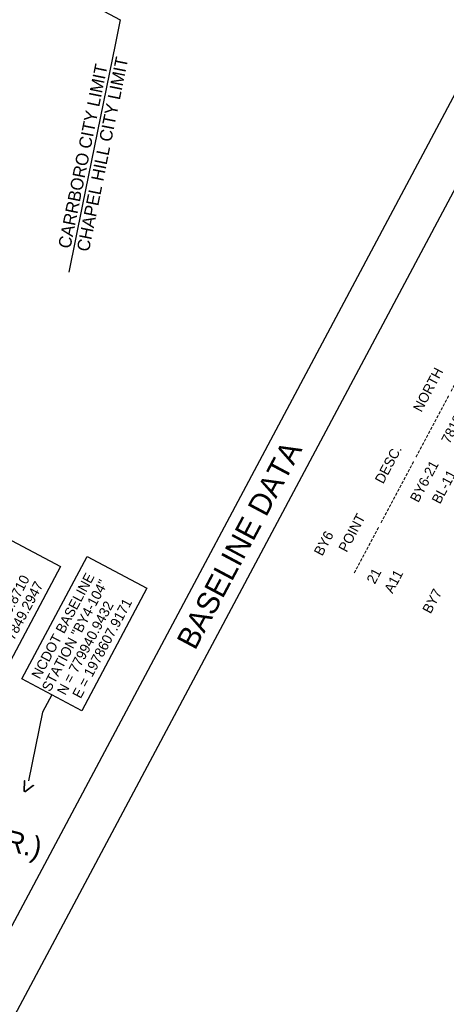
# Model space of a CAD drawing. Extents: x 1970823 to 1988115, y 770601 to 786368.
# Drawn here: x 1978006 to 1979025, y 779627 to 781979 of the extents above; entities that cross this region are included whole.
import ezdxf

# ---------------------------------------------------------------- set-up
doc = ezdxf.new("R2010")
doc.units = 0
for name, color, linetype in [('CTL Sheet Border CELL', 7, 'Continuous'), ('CTL Sheet Text', 7, 'Continuous'), ('CTL Supplemental Horizontal and Vertical Text', 7, 'Continuous'), ('Default', 7, 'Continuous'), ('Old_Level_12', 7, 'Continuous'), ('Old_Level_32', 7, 'Continuous'), ('Old_Level_57', 7, 'Continuous')]:
    doc.layers.add(name, color=color, linetype=linetype)

msp = doc.modelspace()

# ---------------------------------------------------------------- linework, layer by layer
at = {"layer": 'CTL Sheet Border CELL'}
msp.add_lwpolyline([(1977121.9, 778191.4), (1979828.5, 783270.4), (1979922.1, 783220.5), (1977215.6, 778141.6)], close=True, dxfattribs=at)
at = {"layer": 'CTL Supplemental Horizontal and Vertical Text'}
msp.add_lwpolyline([(1978082.3, 780365.9), (1978060.2, 780324.5), (1978026.6, 780160.3)], dxfattribs=at)
at = {"layer": 'Default'}
for points in [[(1977804.4, 780455.6), (1977960.4, 780748.3), (1978103.4, 780672.1), (1977947.4, 780379.4)], [(1978010.8, 780404), (1978166.8, 780696.7), (1978309.7, 780620.5), (1978153.8, 780327.8)]]:
    msp.add_lwpolyline(points, close=True, dxfattribs=at)
at = {"layer": 'Old_Level_12'}
for p, q in [((1978155.6, 782026.6), (1978245.7, 781978.3)), ((1978245.7, 781978.3), (1978234.3, 781922.4)), ((1978234.3, 781922.4), (1978155.2, 781533.5)), ((1978155.2, 781533.5), (1978123, 781375.7))]:
    msp.add_line(p, q, dxfattribs=at)

# ---------------------------------------------------------------- texts
at = {"layer": 'CTL Sheet Text'}
for s, height, rotation, p in [('    POINT          DESC.           NORTH             EAST          ELEVATION          Y6 STATION       OFFSET', 23.75, 61.9471, (1978770.3, 780673.5)), ('21                     BY6-21      781856.6356     1977442.5331           351.82      OUTSIDE PROJECT LIMITS                 ', 23.75, 61.9471, (1978854.2, 780628.8)), ('A11                     BL-11      781869.0105     1977699.7366           337.97         12+36.79         45.08 LT', 23.75, 61.9471, (1978896.1, 780606.5)), ('------------ ---------------- ---------------- ---------------- ---------------- ---------------- ----------------', 23.75, 61.9471, (1978812.3, 780651.1)), ('BASELINE DATA', 52.173, 61.9471, (1978424.7, 780470.5)), ('BY6', 23.75, 61.9471, (1978728.4, 780695.8)), ('BY7', 23.75, 61.9471, (1978987.4, 780557.8)), ('(CULBRETH  DR.)', 50, 346.3665, (1977510.2, 780106.5))]:
    msp.add_text(s, height=height, rotation=rotation, dxfattribs=at).set_placement(p)
at = {"layer": 'CTL Supplemental Horizontal and Vertical Text'}
for s, p in [('NCDOT BASELINE', (1978053.7, 780401.7)), ('N = 780126.8710', (1977914.2, 780425.5)), ('E = 1977849.2947', (1977939.4, 780396.2)), ('STATION "BY4-104"', (1978078.5, 780371.6)), ('N = 779940.9432', (1978114.8, 780363.2)), ('E = 1978607.9171', (1978151.4, 780355.3))]:
    msp.add_text(s, height=24, rotation=61.9471, dxfattribs=at).set_placement(p)
at = {"layer": 'Old_Level_32'}
for s, p in [('CHAPEL HILL CITY LIMIT', (1978171, 781422.8)), ('CARRBORO CITY LIMIT', (1978126.6, 781430.2))]:
    msp.add_text(s, height=30, rotation=78.4961, dxfattribs=at).set_placement(p)
at = {"layer": 'Old_Level_57'}
msp.add_text('>', height=39.1, rotation=241.9613, dxfattribs=at).set_placement((1978013.2, 780167.3))

doc.saveas('drawing.dxf')
